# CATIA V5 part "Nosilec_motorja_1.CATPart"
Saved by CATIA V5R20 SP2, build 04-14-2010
Part number: Nos_M_2
Bounding box of the stored display mesh (mm): x -20 to 20, y -17.5 to 17.5, z 4 to 54
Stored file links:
  C:\Documents and Settings\Administrator\My Documents\Hobi_dokumenti\CAD_CNC\Clap_CATIA\Nosilec_motorja_1.CATPart
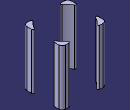
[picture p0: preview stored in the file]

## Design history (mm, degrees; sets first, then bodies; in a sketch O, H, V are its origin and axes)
Set1
  DatumSurface1
  DatumSurface2
Body1 (main body)
  Sketch1 on face of DatumSurface2, origin (0, 0, 4), H (1, 0, 0), V (0, 1, 0)
    line L1 (-20, 17.5) -> (-10.6771, 17.5)
    line L2 (20, 17.5) -> (20, 4.5)
    line L3 (20, -17.5) -> (10.6771, -17.5)
    line L4 (-20, -17.5) -> (-20, -4.5)
    arc A1 centre (0, 0) radius 20.5 from (-20, -4.5) to (-10.6771, -17.5) ccw
    point P5 (20, -4.5)
    line L5 (20, -4.5) -> (20, -17.5)
    point P6 (20, 4.5)
    point P7 (-10.6771, 17.5)
    line L6 (10.6771, 17.5) -> (20, 17.5)
    point P8 (10.6771, 17.5)
    point P9 (-20, 4.5)
    line L7 (-20, 4.5) -> (-20, 17.5)
    point P11 (10.6771, -17.5)
    line L8 (-10.6771, -17.5) -> (-20, -17.5)
    arc A2 centre (0, 0) radius 20.5 from (10.6771, -17.5) to (20, -4.5) ccw
    arc A3 centre (0, 0) radius 20.5 from (-10.6771, 17.5) to (-20, 4.5) ccw
    arc A4 centre (0, 0) radius 20.5 from (20, 4.5) to (10.6771, 17.5) ccw
    distance V L4 = 20
    distance V L2 = 20
    distance H L1 = 17.5
    distance H L3 = 17.5
    radius A1 = 20.5
    horizontal: L1 H, L3 H, L6 H, L8 H
    vertical: L2 V, L4 V, L5 V, L7 V
    coincidence: A1 P5, A1 P6, L2 L5, A1 P7, A1 P8, L1 L6, L4 P9, L4 L7, A1 P11, L3 L8, A1 A2, A2 A3, A2 A4
  Pad1: profile Sketch1, direction (0, 0, 1), length 50
  Fillet1: radius 1, on edge [face of Pad1 from Sketch1.A2 | face of Pad1 from Sketch1.L5]; edge [face of Pad1 from Sketch1.L3 | face of Pad1 from Sketch1.A2]; edge [face of Pad1 from Sketch1.A1 | face of Pad1 from Sketch1.L8]; edge [face of Pad1 from Sketch1.L4 | face of Pad1 from Sketch1.A1]; edge [face of Pad1 from Sketch1.A3 | face of Pad1 from Sketch1.L7]; edge [face of Pad1 from Sketch1.L1 | face of Pad1 from Sketch1.A3]; edge [face of Pad1 from Sketch1.A4 | face of Pad1 from Sketch1.L6]; edge [face of Pad1 from Sketch1.L2 | face of Pad1 from Sketch1.A4]
  Fillet2: radius 3, on edge [face of Pad1 from Sketch1.L8 | face of Pad1 from Sketch1.L4]; edge [face of Pad1 from Sketch1.L5 | face of Pad1 from Sketch1.L3]; edge [face of Pad1 from Sketch1.L6 | face of Pad1 from Sketch1.L2]; edge [face of Pad1 from Sketch1.L7 | face of Pad1 from Sketch1.L1]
